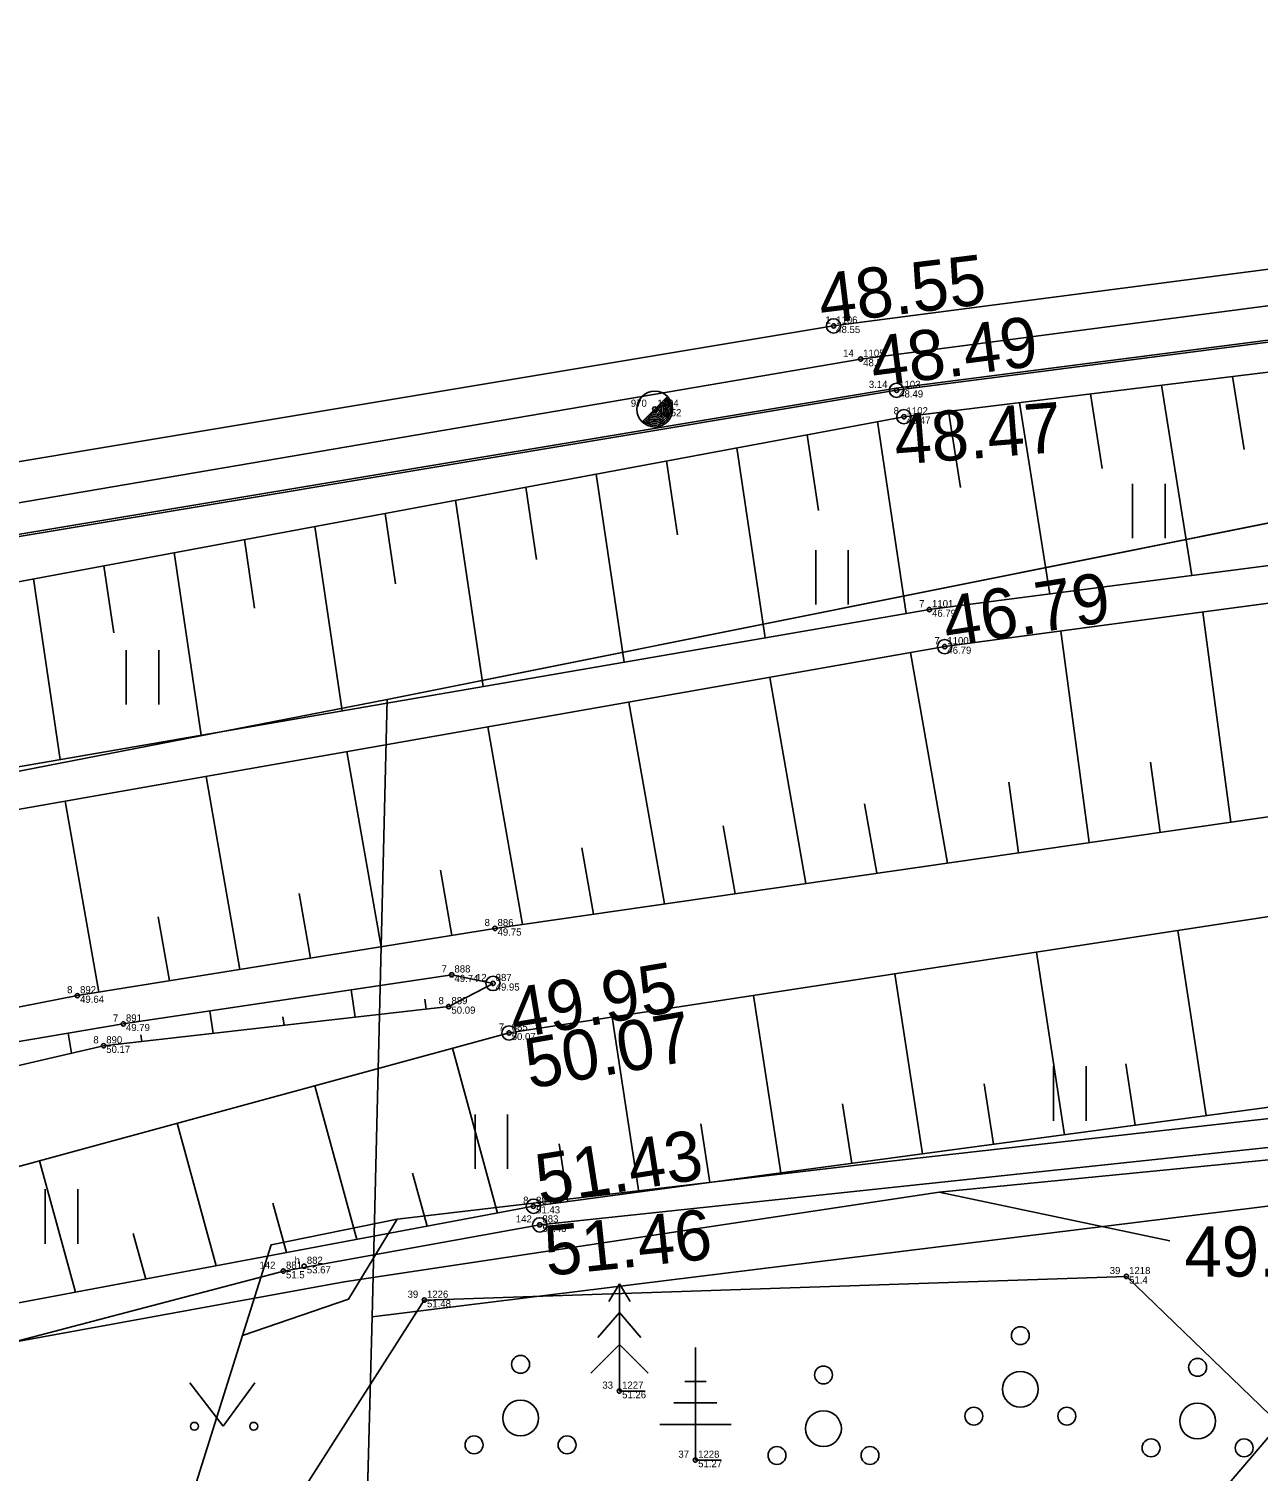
# Model space of a CAD drawing. Extents: x 543497 to 552146, y 6567125 to 6579845.
# Drawn here: x 546568.77 to 546585.95, y 6577770.08 to 6577790.24 of the extents above; entities that cross this region are included whole.
import ezdxf

# ---------------------------------------------------------------- set-up
doc = ezdxf.new("R2010")
doc.units = 0
for name, color, linetype in [('xref_Kangru tee 1_geodeesia$0$ABIJOONIS', 7, 'Continuous'), ('xref_Kangru tee 1_geodeesia$0$AED', 7, 'Continuous'), ('xref_Kangru tee 1_geodeesia$0$HALJASTUS', 7, 'Continuous'), ('xref_Kangru tee 1_geodeesia$0$korgus-EH2000', 7, 'Continuous'), ('xref_Kangru tee 1_geodeesia$0$Liiklus', 7, 'Continuous'), ('xref_Kangru tee 1_geodeesia$0$mootkood', 7, 'Continuous'), ('xref_Kangru tee 1_geodeesia$0$MOOTKORG-eh2000', 7, 'Continuous'), ('xref_Kangru tee 1_geodeesia$0$mootmpunkt', 7, 'Continuous'), ('xref_Kangru tee 1_geodeesia$0$MOOTNR', 7, 'Continuous'), ('xref_Kangru tee 1_geodeesia$0$PIIR', 7, 'Continuous'), ('xref_Kangru tee 1_geodeesia$0$Post', 7, 'Continuous'), ('xref_Kangru tee 1_geodeesia$0$PUU', 7, 'Continuous'), ('xref_Kangru tee 1_geodeesia$0$RELJEEF', 7, 'Continuous'), ('xref_Kangru tee 1_geodeesia$0$SITRASS', 7, 'Continuous'), ('xref_Kangru tee 1_geodeesia$0$TEE', 7, 'Continuous')]:
    doc.layers.add(name, color=color, linetype=linetype)

# ---------------------------------------------------------------- blocks, each defined once
blk = doc.blocks.new('xref_Kangru tee 1_geodeesia$0$plpost')
blk.add_line((-0.354, -0.353), (0.353, 0.354))
blk.add_circle((0, 0), 0.5)
for radius, start, end in [(0.45, 224.8541, 45.0356), (0.4, 224.8427, 45.047), (0.35, 224.8281, 45.0616), (0.3, 224.8087, 45.081), (0.25, 224.7814, 45.1083), (0.2, 224.7406, 45.1491), (0.15, 224.6725, 45.2172), (0.1, 224.5363, 45.3534), (0.05, 224.1278, 45.7619)]:
    blk.add_arc((0, 0), radius, start, end)
blk = doc.blocks.new('xref_Kangru tee 1_geodeesia$0$KUUSK1')
for p, q in [((0, 3), (-0.3, 2.5)), ((0.3, 2.5), (0, 3)), ((0, 3), (0, 0)), ((0, 2.2), (-0.6, 1.5)), ((0.6, 1.5), (0, 2.2)), ((0, 1.3), (-0.8, 0.5)), ((0.8, 0.5), (0, 1.3)), ((0.72, 0), (0, 0))]:
    blk.add_line(p, q)
blk = doc.blocks.new('xref_Kangru tee 1_geodeesia$0$OKASP1')
for p, q in [((0, 0), (0, 3.15)), ((0.3, 2.2), (-0.3, 2.2)), ((0.6, 1.6), (-0.6, 1.6)), ((1, 1), (-1, 1)), ((0.72, 0), (0, 0))]:
    blk.add_line(p, q)
blk = doc.blocks.new('xref_Kangru tee 1_geodeesia$0$PQQSAS')
for centre, radius in [((0, 1.5), 0.25), ((0, 0), 0.5), ((-1.3, -0.75), 0.25), ((1.3, -0.75), 0.25)]:
    blk.add_circle(centre, radius)
blk = doc.blocks.new('xref_Kangru tee 1_geodeesia$0$MURU')
for p, q in [((-0.927, 1.213), (0, 0)), ((0, 0), (0.891, 1.213))]:
    blk.add_line(p, q)
for centre in [(-0.802, 0), (0.856, 0)]:
    blk.add_circle(centre, 0.11)
blk = doc.blocks.new('xref_Kangru tee 1_geodeesia$0$hein')
for p, q in [((-0.455, 0.761), (-0.455, -0.761)), ((0.455, 0.761), (0.455, -0.761))]:
    blk.add_line(p, q)

msp = doc.modelspace()

# ---------------------------------------------------------------- linework, layer by layer
at = {"layer": 'xref_Kangru tee 1_geodeesia$0$ABIJOONIS'}
msp.add_lwpolyline([(546581.496, 6577773.983), (546584.717, 6577773.304)], dxfattribs=at)
at = {"layer": 'xref_Kangru tee 1_geodeesia$0$AED'}
msp.add_lwpolyline([(546619.888, 6577778.288), (546609.506, 6577777.149), (546592.626, 6577775.302), (546575.912, 6577773.527), (546572.329, 6577772.88), (546567.646, 6577771.651), (546545.991, 6577765.945)], dxfattribs=at)
at = {"layer": 'xref_Kangru tee 1_geodeesia$0$HALJASTUS'}
msp.add_lwpolyline([(546584.111, 6577772.806), (546586.252, 6577770.743), (546584.008, 6577768.116), (546577.016, 6577765.276), (546573.44, 6577765.397), (546572.072, 6577766.741), (546572.097, 6577769.027), (546574.299, 6577772.475), (546584.111, 6577772.806)], dxfattribs=at)
at = {"layer": 'xref_Kangru tee 1_geodeesia$0$korgus-EH2000'}
for centre in [(546580.018, 6577786.09), (546580.898, 6577785.19), (546581.001, 6577784.821), (546581.571, 6577781.608), (546575.259, 6577776.901), (546575.483, 6577776.209), (546575.824, 6577773.787), (546575.912, 6577773.527)]:
    msp.add_circle(centre, 0.1, dxfattribs=at)
at = {"layer": 'xref_Kangru tee 1_geodeesia$0$Liiklus'}
for points in [[(546721.913, 6577774.924), (546704.498, 6577780.481), (546687.619, 6577784.545), (546672.912, 6577787.228), (546667.133, 6577788), (546648.703, 6577789.664), (546634.507, 6577790.018), (546619.416, 6577789.618), (546613.24, 6577789.23), (546599.919, 6577788.183), (546580.395, 6577785.626), (546558.693, 6577781.92), (546538.215, 6577778.009)], [(546538.26, 6577777.571), (546558.77, 6577781.533), (546580.893, 6577785.218), (546600.058, 6577787.695), (546613.274, 6577788.837)]]:
    msp.add_lwpolyline(points, dxfattribs=at)
at = {"layer": 'xref_Kangru tee 1_geodeesia$0$mootmpunkt'}
for centre in [(546580.018, 6577786.09), (546580.395, 6577785.626), (546580.898, 6577785.19), (546577.519, 6577784.927), (546581.001, 6577784.821), (546581.357, 6577782.125), (546581.571, 6577781.608), (546575.285, 6577777.669), (546574.683, 6577777.021), (546569.451, 6577776.73), (546575.259, 6577776.901), (546574.641, 6577776.578), (546570.092, 6577776.335), (546575.483, 6577776.209), (546569.817, 6577776.03), (546575.824, 6577773.787), (546575.912, 6577773.527), (546572.62, 6577772.949), (546572.329, 6577772.88), (546584.111, 6577772.806), (546574.299, 6577772.475), (546577.026, 6577771.204), (546578.088, 6577770.239)]:
    msp.add_circle(centre, 0.03, dxfattribs=at)
at = {"layer": 'xref_Kangru tee 1_geodeesia$0$PIIR'}
for points in [[(546508.03, 6577841.48), (546527.76, 6577842.6), (546535.64, 6577829.79), (546540.71, 6577817.81), (546551.12, 6577809.99), (546561.59, 6577802.16), (546622.52, 6577814.88), (546633.51, 6577792.62), (546608.95, 6577787.91), (546573.78, 6577780.87), (546521.59, 6577770.69), (546316.12, 6577725.86), (546173.38, 6577691.06), (546034.23, 6577654.21), (545899.95, 6577611.29), (545780.54, 6577566.57), (545623.97, 6577499.02), (545555.77, 6577467.67), (545385.83, 6577376.92), (545249.19, 6577295.85), (545250.22, 6577289.9), (544980.83, 6577118.49)], [(546608.95, 6577787.91), (546613.94, 6577777.23), (546573.57, 6577772.24), (546573.78, 6577780.87), (546608.95, 6577787.91)], [(546741.41, 6577111.25), (546683.61, 6577317.78), (546673.81, 6577353.39), (546663.96, 6577389.17), (546660.51, 6577401.7), (546647.19, 6577450.09), (546634.65, 6577495.62), (546625.43, 6577526.07), (546609.43, 6577571.52), (546593.21, 6577617.62), (546579.42, 6577656.79), (546562.86, 6577702.03), (546544.17, 6577758.03), (546521.59, 6577770.69), (546573.78, 6577780.87), (546573.57, 6577772.24), (546572.44, 6577729.89), (546568.55, 6577727.96), (546603, 6577632.08), (546611.62, 6577607.53), (546638.72, 6577530.39), (546648.14, 6577499.5), (546658.9, 6577460.58), (546749.51, 6577130.19)], [(546572.44, 6577729.89), (546573.57, 6577772.24), (546613.94, 6577777.23), (546617.58, 6577769.56), (546644.8, 6577768), (546649.32, 6577758.15), (546629.37, 6577744.28), (546606.33, 6577728.26), (546597.82, 6577742.14), (546572.44, 6577729.89)]]:
    msp.add_lwpolyline(points, dxfattribs=at)
at = {"layer": 'xref_Kangru tee 1_geodeesia$0$RELJEEF'}
for p, q in [((546584.6, 6577785.262), (546585.023, 6577782.601)), ((546585.592, 6577785.383), (546585.755, 6577784.364)), ((546582.615, 6577785.019), (546583.04, 6577782.343)), ((546583.607, 6577785.14), (546583.773, 6577784.097)), ((546581.622, 6577784.897), (546581.792, 6577783.83)), ((546580.633, 6577784.752), (546581.031, 6577782.069)), ((546579.65, 6577784.569), (546579.807, 6577783.511)), ((546578.667, 6577784.386), (546579.061, 6577781.729)), ((546576.701, 6577784.02), (546577.09, 6577781.389)), ((546577.684, 6577784.203), (546577.837, 6577783.169)), ((546575.718, 6577783.836), (546575.867, 6577782.827)), ((546574.735, 6577783.653), (546575.12, 6577781.049)), ((546573.751, 6577783.47), (546573.897, 6577782.485)), ((546572.768, 6577783.287), (546573.15, 6577780.709)), ((546571.785, 6577783.104), (546571.928, 6577782.143)), ((546570.802, 6577782.921), (546571.18, 6577780.369)), ((546569.819, 6577782.737), (546569.958, 6577781.801)), ((546568.836, 6577782.554), (546569.21, 6577780.029)), ((546585.57, 6577779.155), (546585.177, 6577782.091)), ((546583.591, 6577778.869), (546583.195, 6577781.825)), ((546581.611, 6577778.583), (546581.095, 6577781.524)), ((546579.632, 6577778.297), (546579.126, 6577781.178)), ((546577.653, 6577778.011), (546577.157, 6577780.832)), ((546575.673, 6577777.725), (546575.188, 6577780.486)), ((546573.698, 6577777.413), (546573.218, 6577780.14)), ((546584.581, 6577779.012), (546584.449, 6577779.994)), ((546571.723, 6577777.096), (546571.249, 6577779.794)), ((546582.601, 6577778.726), (546582.469, 6577779.715)), ((546569.748, 6577776.778), (546569.279, 6577779.448)), ((546580.622, 6577778.44), (546580.451, 6577779.411)), ((546578.642, 6577778.154), (546578.475, 6577779.105)), ((546576.663, 6577777.868), (546576.499, 6577778.798)), ((546574.685, 6577777.572), (546574.524, 6577778.486)), ((546572.71, 6577777.255), (546572.551, 6577778.159)), ((546570.736, 6577776.937), (546570.578, 6577777.831)), ((546585.226, 6577775.054), (546584.829, 6577777.641)), ((546583.244, 6577774.787), (546582.853, 6577777.338)), ((546581.262, 6577774.52), (546580.876, 6577777.035)), ((546573.334, 6577776.429), (546573.277, 6577776.811)), ((546574.327, 6577776.542), (546574.306, 6577776.681)), ((546579.28, 6577774.253), (546578.9, 6577776.732)), ((546571.346, 6577776.204), (546571.3, 6577776.515)), ((546572.34, 6577776.317), (546572.323, 6577776.432)), ((546577.297, 6577773.986), (546576.923, 6577776.43)), ((546569.368, 6577775.926), (546569.321, 6577776.205)), ((546570.353, 6577776.091), (546570.339, 6577776.183)), ((546575.32, 6577773.692), (546574.693, 6577775.994)), ((546584.235, 6577774.92), (546584.104, 6577775.777)), ((546573.354, 6577773.323), (546572.769, 6577775.47)), ((546582.253, 6577774.653), (546582.123, 6577775.498)), ((546580.271, 6577774.386), (546580.143, 6577775.219)), ((546571.388, 6577772.955), (546570.846, 6577774.946)), ((546578.289, 6577774.119), (546578.163, 6577774.94)), ((546576.306, 6577773.852), (546576.183, 6577774.661)), ((546569.423, 6577772.586), (546568.922, 6577774.422)), ((546574.337, 6577773.508), (546574.135, 6577774.249)), ((546572.371, 6577773.139), (546572.183, 6577773.829)), ((546570.405, 6577772.77), (546570.232, 6577773.408))]:
    msp.add_line(p, q, dxfattribs=at)
for points in [[(546538.34, 6577776.988), (546558.87, 6577780.697), (546581.001, 6577784.821), (546600.069, 6577787.156), (546619.252, 6577788.758)], [(546538.814, 6577774.564), (546558.883, 6577778.247), (546581.357, 6577782.125), (546600.081, 6577784.554), (546618.535, 6577786.262), (546633.012, 6577786.921), (546648.115, 6577786.579), (546666.374, 6577784.262), (546672.405, 6577783.73), (546686.612, 6577781.238), (546689.643, 6577780.706), (546693.637, 6577779.753), (546703.929, 6577777.342), (546710.71, 6577775.098), (546720.871, 6577771.555)], [(546538.896, 6577773.872), (546559.049, 6577777.65), (546581.571, 6577781.608), (546600.058, 6577784.083), (546618.575, 6577785.829), (546632.878, 6577786.269), (546648.145, 6577785.891), (546666.337, 6577783.931), (546672.337, 6577783.228), (546686.505, 6577780.733), (546689.529, 6577780.165), (546693.523, 6577779.183), (546703.735, 6577776.88), (546710.628, 6577774.799), (546720.7, 6577771.177)], [(546554.904, 6577773.96), (546559.746, 6577774.952), (546563.529, 6577775.486), (546566.104, 6577776.076), (546569.451, 6577776.73), (546575.285, 6577777.669), (546591.928, 6577780.074), (546609.002, 6577782.024), (546618.326, 6577782.861), (546622.722, 6577782.991), (546628.579, 6577783.379), (546640.222, 6577783.284), (546642.311, 6577782.972), (546644.296, 6577782.453), (546645.105, 6577782.242), (546655.773, 6577781.108), (546661.524, 6577780.531), (546663.681, 6577779.627)], [(546663.681, 6577779.627), (546661.025, 6577779.482), (546655.667, 6577780.24), (546645.195, 6577781.158), (546642.472, 6577782.453), (546639.822, 6577782.844), (546628.438, 6577782.653), (546623.553, 6577781.976), (546622.345, 6577781.625), (546621.629, 6577780.852), (546620.046, 6577780.644), (546609.199, 6577780.378), (546592.284, 6577778.783), (546575.483, 6577776.209), (546566.953, 6577773.885), (546564.502, 6577773.16), (546560.282, 6577772.223), (546558.324, 6577771.967), (546554.183, 6577771.468), (546550.857, 6577770.53)], [(546550.727, 6577769.706), (546551.249, 6577769.491), (546567.458, 6577772.217), (546575.824, 6577773.787), (546592.716, 6577776.063), (546609.093, 6577777.913), (546620.403, 6577778.527), (546622.24, 6577778.664), (546623.137, 6577779.453), (546623.473, 6577780.609), (546628.431, 6577781.294), (546639.632, 6577780.958), (546641.087, 6577780.8), (546642.154, 6577779.459), (546644.484, 6577778.868), (546654.742, 6577777.987), (546663.525, 6577777.379)], [(546575.259, 6577776.901), (546574.683, 6577777.021), (546570.092, 6577776.335), (546566.16, 6577775.672), (546563.535, 6577775.068), (546562.505, 6577774.741)], [(546562.505, 6577774.741), (546563.954, 6577774.703), (546566.516, 6577775.267), (546569.817, 6577776.03), (546574.641, 6577776.578), (546575.259, 6577776.901)]]:
    msp.add_lwpolyline(points, dxfattribs=at)
at = {"layer": 'xref_Kangru tee 1_geodeesia$0$SITRASS'}
for points in [[(546616.772, 6577777.542), (546615.216, 6577778.191), (546602.787, 6577776.827), (546592.36, 6577775.701), (546587.927, 6577775.219), (546580.777, 6577774.412), (546573.919, 6577773.607), (546573.241, 6577772.489), (546571.76, 6577771.98)], [(546535.945, 6577765.191), (546545.774, 6577767.54), (546561.492, 6577770.597), (546573.177, 6577772.732), (546581.496, 6577773.983), (546601.337, 6577775.932), (546614.05, 6577777.466), (546620.283, 6577777.55), (546631.954, 6577777.234), (546639.759, 6577775.901), (546642.232, 6577774.863), (546647.939, 6577768.847), (546651.396, 6577764.746), (546652.558, 6577762.284)], [(546535.945, 6577765.191), (546545.774, 6577767.54), (546561.492, 6577770.597), (546573.177, 6577772.732), (546581.496, 6577773.983), (546601.337, 6577775.932), (546614.05, 6577777.466), (546620.283, 6577777.55), (546631.954, 6577777.234), (546639.759, 6577775.901)], [(546573.919, 6577773.607), (546572.16, 6577773.249), (546571.76, 6577771.98), (546570.312, 6577767.388), (546567.217, 6577758.248), (546566.268, 6577755.637), (546566.058, 6577755.169)]]:
    msp.add_lwpolyline(points, dxfattribs=at)
at = {"layer": 'xref_Kangru tee 1_geodeesia$0$TEE'}
for points in [[(546538.072, 6577778.474), (546558.355, 6577782.483), (546580.018, 6577786.09), (546599.801, 6577788.666), (546619.258, 6577790.187), (546634.544, 6577790.675), (546648.905, 6577790.198), (546667.188, 6577788.59), (546673.08, 6577787.807), (546687.848, 6577785.135), (546704.62, 6577781.061), (546722.283, 6577775.399)], [(546704.364, 6577779.548), (546687.303, 6577783.754), (546672.831, 6577786.155), (546666.989, 6577786.944), (546648.576, 6577788.953), (546634.52, 6577789.12), (546619.252, 6577788.758), (546600.059, 6577787.667), (546580.898, 6577785.19), (546558.777, 6577781.504), (546538.268, 6577777.542)]]:
    msp.add_lwpolyline(points, dxfattribs=at)

# ---------------------------------------------------------------- block references
at = {"layer": 'xref_Kangru tee 1_geodeesia$0$HALJASTUS', "xscale": 0.5, "yscale": 0.5}
for name, p in [('xref_Kangru tee 1_geodeesia$0$hein', (546584.424, 6577783.504)), ('xref_Kangru tee 1_geodeesia$0$hein', (546579.996, 6577782.576)), ('xref_Kangru tee 1_geodeesia$0$hein', (546570.361, 6577781.179)), ('xref_Kangru tee 1_geodeesia$0$hein', (546583.321, 6577775.363)), ('xref_Kangru tee 1_geodeesia$0$hein', (546575.235, 6577774.69)), ('xref_Kangru tee 1_geodeesia$0$hein', (546569.23, 6577773.644)), ('xref_Kangru tee 1_geodeesia$0$PQQSAS', (546582.628, 6577771.229)), ('xref_Kangru tee 1_geodeesia$0$PQQSAS', (546575.644, 6577770.827)), ('xref_Kangru tee 1_geodeesia$0$PQQSAS', (546579.877, 6577770.679)), ('xref_Kangru tee 1_geodeesia$0$PQQSAS', (546585.105, 6577770.785)), ('xref_Kangru tee 1_geodeesia$0$MURU', (546571.487, 6577770.712))]:
    msp.add_blockref(name, p, dxfattribs=at)
at = {"layer": 'xref_Kangru tee 1_geodeesia$0$Post', "xscale": 0.5, "yscale": 0.5}
msp.add_blockref('xref_Kangru tee 1_geodeesia$0$plpost', (546577.519, 6577784.927), dxfattribs=at)
at = {"layer": 'xref_Kangru tee 1_geodeesia$0$PUU', "xscale": 0.5, "yscale": 0.5}
for name, p in [('xref_Kangru tee 1_geodeesia$0$KUUSK1', (546577.026, 6577771.204)), ('xref_Kangru tee 1_geodeesia$0$OKASP1', (546578.088, 6577770.239))]:
    msp.add_blockref(name, p, dxfattribs=at)

# ---------------------------------------------------------------- texts
at = {"layer": 'xref_Kangru tee 1_geodeesia$0$ABIJOONIS'}
msp.add_text('49.34', height=0.7, dxfattribs=at).set_placement((546584.923, 6577772.804))
at = {"layer": 'xref_Kangru tee 1_geodeesia$0$korgus-EH2000'}
for s, rotation, p in [(' 48.55 ', 7.0112, (546579.594, 6577786.083)), (' 48.49 ', 7.4092, (546580.324, 6577785.203)), (' 48.47 ', 4.4734, (546580.632, 6577784.129)), (' 46.79 ', 8.8506, (546581.349, 6577781.564)), (' 49.95 ', 9.5565, (546575.301, 6577776.086)), (' 50.07 ', 9.9051, (546575.513, 6577775.382)), (' 51.43 ', 8.9726, (546575.655, 6577773.768)), (' 51.46 ', 5.967, (546575.756, 6577772.785))]:
    msp.add_text(s, height=0.7, rotation=rotation, dxfattribs=at).set_placement(p)
at = {"layer": 'xref_Kangru tee 1_geodeesia$0$mootkood'}
for s, p in [(' 1', (546579.866, 6577786.123)), (' 14', (546580.114, 6577785.659)), (' 3.14', (546580.474, 6577785.223)), (' 970', (546577.148, 6577784.96)), (' 8', (546580.82, 6577784.854)), (' 7', (546581.176, 6577782.158)), (' 7', (546581.39, 6577781.641)), (' 8', (546575.104, 6577777.702)), (' 7', (546574.502, 6577777.054)), (' 12', (546574.983, 6577776.934)), (' 8', (546569.27, 6577776.763)), (' 8', (546574.46, 6577776.611)), (' 7', (546569.911, 6577776.368)), (' 8', (546569.636, 6577776.063)), (' 7', (546575.302, 6577776.242)), (' 8', (546575.643, 6577773.82)), (' 142', (546575.541, 6577773.56)), (' 142', (546571.958, 6577772.913)), (' h', (546572.449, 6577772.982)), (' 39', (546583.84, 6577772.839)), (' 39', (546574.028, 6577772.508)), (' 33', (546576.75, 6577771.237)), (' 37', (546577.812, 6577770.272))]:
    msp.add_text(s, height=0.1, dxfattribs=at).set_placement(p)
at = {"layer": 'xref_Kangru tee 1_geodeesia$0$MOOTKORG-eh2000'}
for s, p in [(' 48.55', (546580.018, 6577785.99)), (' 48.5', (546580.395, 6577785.526)), (' 48.49', (546580.898, 6577785.09)), (' 48.52', (546577.519, 6577784.827)), (' 48.47', (546581.001, 6577784.721)), (' 46.79', (546581.357, 6577782.025)), (' 46.79', (546581.571, 6577781.508)), (' 49.75', (546575.285, 6577777.569)), (' 49.74', (546574.683, 6577776.921)), (' 49.95', (546575.259, 6577776.801)), (' 49.64', (546569.451, 6577776.63)), (' 50.09', (546574.641, 6577776.478)), (' 49.79', (546570.092, 6577776.235)), (' 50.07', (546575.483, 6577776.109)), (' 50.17', (546569.817, 6577775.93)), (' 51.43', (546575.824, 6577773.687)), (' 51.46', (546575.912, 6577773.427)), (' 53.67', (546572.62, 6577772.849)), (' 51.5', (546572.329, 6577772.78)), (' 51.4', (546584.111, 6577772.706)), (' 51.48', (546574.299, 6577772.375)), (' 51.26', (546577.026, 6577771.104)), (' 51.27', (546578.088, 6577770.139))]:
    msp.add_text(s, height=0.1, dxfattribs=at).set_placement(p)
at = {"layer": 'xref_Kangru tee 1_geodeesia$0$MOOTNR'}
for s, p in [(' 1106', (546580.018, 6577786.123)), (' 1105', (546580.395, 6577785.659)), (' 1103', (546580.898, 6577785.223)), (' 1104', (546577.519, 6577784.96)), (' 1102', (546581.001, 6577784.854)), (' 1101', (546581.357, 6577782.158)), (' 1100', (546581.571, 6577781.641)), (' 886', (546575.285, 6577777.702)), (' 888', (546574.683, 6577777.054)), (' 887', (546575.259, 6577776.934)), (' 892', (546569.451, 6577776.763)), (' 889', (546574.641, 6577776.611)), (' 891', (546570.092, 6577776.368)), (' 890', (546569.817, 6577776.063)), (' 885', (546575.483, 6577776.242)), (' 884', (546575.824, 6577773.82)), (' 883', (546575.912, 6577773.56)), (' 881', (546572.329, 6577772.913)), (' 882', (546572.62, 6577772.982)), (' 1218', (546584.111, 6577772.839)), (' 1226', (546574.299, 6577772.508)), (' 1227', (546577.026, 6577771.237)), (' 1228', (546578.088, 6577770.272))]:
    msp.add_text(s, height=0.1, dxfattribs=at).set_placement(p)

doc.saveas('drawing.dxf')
